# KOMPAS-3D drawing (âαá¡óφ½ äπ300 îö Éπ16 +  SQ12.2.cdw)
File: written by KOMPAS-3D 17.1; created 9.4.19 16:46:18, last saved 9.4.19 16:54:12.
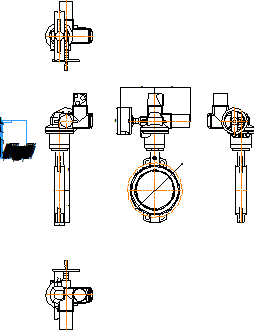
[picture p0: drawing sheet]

Sheet 1: A4, portrait

Title block, sheet 1: name: Гранвэл Ду300 МФ Ру16 + / SQ12.2; material: Внимание! Данный продукт является объектом авторского права ООО «Торговый Дом АДЛ». / Запрещается изменение, копирование, распространение / (в том числе путем копирования на другие сайты и ресурсы в Интернете) / или любое иное использование информации и объектов без предварительного / согласия правообладателя (ООО «Торговый Дом АДЛ»).; mass: 67,5; sheets: 1; organisation: ООО "Торговый дом АДЛ"; sheet format: A4; stored path: \\adlc.lan\data\АДЛ_ПКД\3D-модели\ADL production\Дисковые поворотные затворы ГРАНВЭЛ\межфланцевый с эл.приводом Auma Ру 16\KOMPAS 2D\Гранвэл Ду300 МФ Ру16 +  SQ12.2.cdw

Views: Вид 1, Проекционный вид 2, Проекционный вид 3, Проекционный вид 4, Вид 5
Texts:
  user
Dimensions and other numbers on the sheet: 308; 240; 78; 264; 253,7; 200; 410; 1:1; 1; 67,5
